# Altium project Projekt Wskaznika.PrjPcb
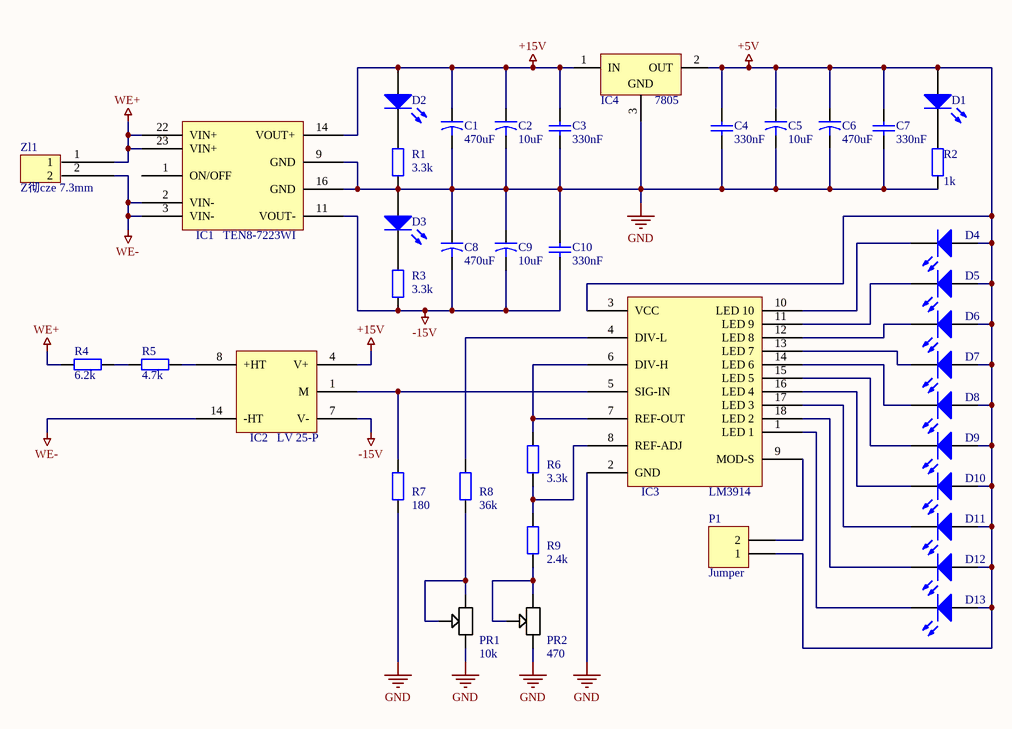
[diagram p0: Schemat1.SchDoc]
1 sheet, 40 parts. Net scope: global (net labels, ports and power ports of the same name join across sheets).
Board file: Wskaznik.PcbDoc

## Sheet Schemat1.SchDoc
size A4; PageSetup: Record=PageOptions|CenterHorizontal=True|CenterVertical=True|PrintScale=1.00|XCorrection=1.00|YCorrection=1.00|PrintKind=0|BorderSize=5000000|LeftOffset=0|BottomOffset=0|Orientation=2|PaperLength=1000|PaperWidth=1000|Scale=100|PaperSource=7|PrintQuality=-4|MediaType=1|DitherType=10|PaperKind=A4|PrintScaleMode=1

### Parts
C1  value 470uF  [RB5-10.5]
C2  value 10uF  [Elektrolit 2.5]
C3  value 330nF  [poliestrowy]
C4  value 330nF  [poliestrowy]
C5  value 10uF  [Elektrolit 2.5]
C6  value 470uF  [RB5-10.5]
C7  value 330nF  [poliestrowy]
C8  value 470uF  [RB5-10.5]
C9  value 10uF  [Elektrolit 2.5]
C10  value 330nF  [poliestrowy]
D1  Dioda LED  [dioda led]  (value not drawn)
D2  Dioda LED  [dioda led]  (value not drawn)
D3  Dioda LED  [dioda led]  (value not drawn)
D4  (no value)  [LED-1]
D5  (no value)  [LED-1]
D6  (no value)  [LED-1]
D7  (no value)  [LED-1]
D8  (no value)  [LED-1]
D9  (no value)  [LED-1]
D10  (no value)  [LED-1]
D11  (no value)  [LED-1]
D12  (no value)  [LED-1]
D13  (no value)  [LED-1]
IC1  TEN8-7223WI  [TRACO-DIP24]
IC2  LV 25-P  [DIP14 LEM NEW]
IC3  LM3914  [DIP18]
IC4  7805  [ISOWATT220AB]
P1  Jumper  [HDR1X2]
PR1  10k  [PCBComponent_1 - duplicate]
PR2  470  [PCBComponent_1 - duplicate]
R1  value 3.3k  [AXIAL-0.3]  (hidden comment: Rezystor)
R2  value 1k  [AXIAL-0.3]  (hidden comment: Rezystor)
R3  value 3.3k  [AXIAL-0.3]  (hidden comment: Rezystor)
R4  value 6.2k  [duzy pionowo]  (hidden comment: Rezystor)
R5  value 4.7k  [duzy pionowo]  (hidden comment: Rezystor)
R6  value 3.3k  [AXIAL-0.3]  (hidden comment: Rezystor)
R7  value 180  [AXIAL-0.4]
R8  value 36k  [AXIAL-0.3]  (hidden comment: Rezystor)
R9  value 2.4k  [AXIAL-0.3]  (hidden comment: Rezystor)
Zl1  Z彻cze 7.3mm  [PCBComponent_1 - duplicate1]

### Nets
+5V: C4.2 C5.1 C6.1 C7.2 D1.1(A) D4.1(A) D5.1(A) D6.1(A) D7.1(A) D8.1(A) D9.1(A) D10.1(A) D11.1(A) D12.1(A) D13.1(A) IC3.3(VCC) IC4.2(OUT) P1.1
+15V: C1.1 C2.1 C3.2 D2.1(A) IC1.14(VOUT+) IC2.4(V+) IC4.1(IN)
-15V: C8.2 C9.2 C10.1 IC1.11(VOUT-) IC2.7(V-) R3.1
GND: C1.2 C2.2 C3.1 C4.1 C5.2 C6.2 C7.1 C8.1 C9.1 C10.2 D3.1(A) IC1.9(GND) IC1.16(GND) IC3.2(GND) IC4.3(GND) PR1.1 PR2.1 R1.1 R2.1 R7.1
WE+: IC1.22(VIN+) IC1.23(VIN+) R4.1 Zl1.1
WE-: IC1.2(VIN-) IC1.3(VIN-) IC2.14(-HT) Zl1.2
NetD1_2: D1.2(K) R2.2
NetD2_2: D2.2(K) R1.2
NetD3_2: D3.2(K) R3.2
NetD4_2: D4.2(K) IC3.10(LED_10)
NetD5_2: D5.2(K) IC3.11(LED_9)
NetD6_2: D6.2(K) IC3.12(LED_8)
NetD7_2: D7.2(K) IC3.13(LED_7)
NetD8_2: D8.2(K) IC3.14(LED_6)
NetD9_2: D9.2(K) IC3.15(LED_5)
NetD10_2: D10.2(K) IC3.16(LED_4)
NetD11_2: D11.2(K) IC3.17(LED_3)
NetD12_2: D12.2(K) IC3.18(LED_2)
NetD13_2: D13.2(K) IC3.1(LED_1)
NetIC2_1: IC2.1(M) IC3.5(SIG-IN) R7.2
NetIC2_8: IC2.8(+HT) R5.1
NetIC3_4: IC3.4(DIV-L) R8.2
NetIC3_6: IC3.6(DIV-H) IC3.7(REF-OUT) R6.2
NetIC3_8: IC3.8(REF-ADJ) R6.1 R9.2
NetIC3_9: IC3.9(MOD-S) P1.2
NetPR1_2: PR1.2 PR1.3 R8.1
NetPR2_2: PR2.2 PR2.3 R9.1
NetR4_2: R4.2 R5.2

Not connected (* = marked no-connect by the designer): IC1 1(ON/OFF)

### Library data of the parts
C1 C2 C5 C6 C8 C9 = Kondensator el.
C3 C10 = Kondensator
C4 C7 = Kondensator: 330nF
D1-D3 = Dioda LED: LED
D4-D13 = LED1: Typical RED GaAs LED
IC1 = TEN 8-7223WI
IC3 = LM3914: LED BAR DRIVER
IC4 = L78M05CP: Positive Voltage Regulator; Note: Tab is connected to pin 3 (GND).
P1 = Header 2: Header, 2-Pin
PR1 PR2 = Potencjometr ELFA
R7 = Res2: Resistor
